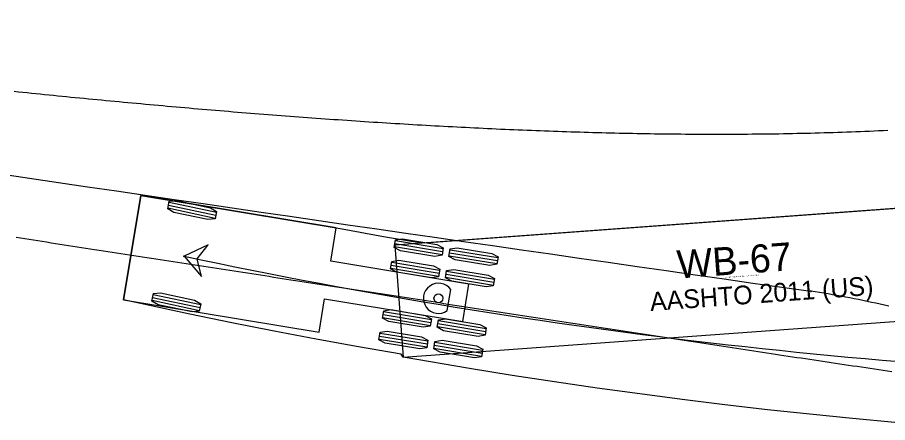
# Model space of a CAD drawing. Extents: x 2175591 to 2194071, y 76570 to 86955.
# Drawn here: x 2192756.8 to 2192822.6, y 86760 to 86790.7 of the extents above; entities that cross this region are included whole.
import ezdxf

# ---------------------------------------------------------------- set-up
doc = ezdxf.new("R2010")
doc.units = 0
doc.layers.add('-NOPLT', color=7, linetype='Continuous')
doc.layers.add('C-UTIL-STRM-TEXT', color=7, linetype='Continuous')

msp = doc.modelspace()

# ---------------------------------------------------------------- linework, layer by layer
at = {"layer": '-NOPLT'}
for points in [[(2192756.506, 86785.068), (2192756.837, 86785.034), (2192757.168, 86785), (2192757.499, 86784.966), (2192757.83, 86784.933), (2192758.161, 86784.899), (2192758.492, 86784.866), (2192758.824, 86784.833), (2192759.155, 86784.799), (2192759.486, 86784.766), (2192759.817, 86784.733), (2192760.149, 86784.701), (2192760.48, 86784.668), (2192760.811, 86784.635), (2192761.142, 86784.603), (2192761.474, 86784.571), (2192761.805, 86784.538), (2192762.137, 86784.506), (2192762.468, 86784.474), (2192762.799, 86784.443), (2192763.131, 86784.411), (2192763.462, 86784.379), (2192763.794, 86784.348), (2192764.125, 86784.317), (2192764.457, 86784.286), (2192764.788, 86784.255), (2192765.119, 86784.224), (2192765.451, 86784.193), (2192765.782, 86784.162), (2192766.114, 86784.132), (2192766.445, 86784.102), (2192766.777, 86784.071), (2192767.109, 86784.041), (2192767.44, 86784.011), (2192767.772, 86783.982), (2192768.103, 86783.952), (2192768.435, 86783.923), (2192768.766, 86783.893), (2192769.098, 86783.864), (2192769.43, 86783.835), (2192769.761, 86783.806), (2192770.093, 86783.778), (2192770.424, 86783.749), (2192770.756, 86783.721), (2192771.088, 86783.692), (2192771.419, 86783.664), (2192771.751, 86783.636), (2192772.083, 86783.609), (2192772.415, 86783.581), (2192772.746, 86783.553), (2192773.078, 86783.526), (2192773.41, 86783.499), (2192773.742, 86783.472), (2192774.073, 86783.445), (2192774.405, 86783.419), (2192774.737, 86783.392), (2192775.069, 86783.366), (2192775.4, 86783.34), (2192775.732, 86783.314), (2192776.064, 86783.288), (2192776.396, 86783.262), (2192776.728, 86783.237), (2192777.06, 86783.211), (2192777.392, 86783.186), (2192777.724, 86783.161), (2192778.055, 86783.137), (2192778.387, 86783.112), (2192778.719, 86783.088), (2192779.051, 86783.063), (2192779.383, 86783.039), (2192779.715, 86783.016), (2192780.047, 86782.992), (2192780.379, 86782.968), (2192780.711, 86782.945), (2192781.043, 86782.922), (2192781.375, 86782.899), (2192781.707, 86782.876), (2192782.039, 86782.854), (2192782.371, 86782.832), (2192782.703, 86782.81), (2192783.035, 86782.788), (2192783.368, 86782.766), (2192783.7, 86782.744), (2192784.032, 86782.723), (2192784.364, 86782.702), (2192784.696, 86782.681), (2192785.028, 86782.66), (2192785.36, 86782.64), (2192785.692, 86782.62), (2192786.025, 86782.6), (2192786.357, 86782.58), (2192786.689, 86782.56), (2192787.021, 86782.541), (2192787.353, 86782.521), (2192787.686, 86782.502), (2192788.018, 86782.484), (2192788.35, 86782.465), (2192788.682, 86782.447), (2192789.014, 86782.429), (2192789.347, 86782.411), (2192789.679, 86782.393), (2192790.011, 86782.376), (2192790.343, 86782.359), (2192790.676, 86782.342), (2192791.008, 86782.325), (2192791.34, 86782.309), (2192791.673, 86782.293), (2192792.005, 86782.277), (2192792.337, 86782.261), (2192792.67, 86782.245), (2192793.002, 86782.23), (2192793.334, 86782.215), (2192793.667, 86782.2), (2192793.999, 86782.186), (2192794.331, 86782.172), (2192794.664, 86782.158), (2192794.996, 86782.144), (2192795.329, 86782.131), (2192795.661, 86782.117), (2192795.993, 86782.104), (2192796.326, 86782.092), (2192796.658, 86782.079), (2192796.991, 86782.067), (2192797.323, 86782.055), (2192797.655, 86782.044), (2192797.988, 86782.032), (2192798.32, 86782.021), (2192798.653, 86782.011), (2192798.985, 86782), (2192799.318, 86781.99), (2192799.65, 86781.98), (2192799.983, 86781.97), (2192800.315, 86781.961), (2192800.648, 86781.952), (2192800.98, 86781.943), (2192801.313, 86781.935), (2192801.645, 86781.927), (2192801.978, 86781.919), (2192802.311, 86781.911), (2192802.643, 86781.904), (2192802.976, 86781.897), (2192803.309, 86781.891), (2192803.642, 86781.884), (2192803.975, 86781.878), (2192804.308, 86781.873), (2192804.641, 86781.867), (2192804.974, 86781.862), (2192805.307, 86781.857), (2192805.641, 86781.853), (2192805.974, 86781.849), (2192806.308, 86781.845), (2192806.642, 86781.842), (2192806.976, 86781.839), (2192807.31, 86781.836), (2192807.645, 86781.834), (2192807.979, 86781.832), (2192808.314, 86781.83), (2192808.649, 86781.829), (2192808.985, 86781.828), (2192809.32, 86781.827), (2192809.656, 86781.827), (2192809.992, 86781.827), (2192810.328, 86781.827), (2192810.665, 86781.828), (2192811.002, 86781.829), (2192811.339, 86781.831), (2192811.677, 86781.833), (2192812.014, 86781.835), (2192812.353, 86781.838), (2192812.691, 86781.841), (2192813.03, 86781.845), (2192813.369, 86781.849), (2192813.709, 86781.853), (2192814.048, 86781.858), (2192814.388, 86781.863), (2192814.729, 86781.869), (2192815.07, 86781.875), (2192815.411, 86781.882), (2192815.752, 86781.889), (2192816.094, 86781.896), (2192816.435, 86781.904), (2192816.778, 86781.912), (2192817.12, 86781.921), (2192817.463, 86781.93), (2192817.806, 86781.94), (2192818.149, 86781.95), (2192818.492, 86781.96), (2192818.836, 86781.971), (2192819.179, 86781.983), (2192819.523, 86781.995), (2192819.867, 86782.007), (2192820.211, 86782.021), (2192820.556, 86782.034), (2192820.9, 86782.048), (2192821.244, 86782.063), (2192821.589, 86782.078), (2192821.933, 86782.093), (2192822.277, 86782.109), (2192822.622, 86782.126)], [(2192793.995, 86768.245), (2192793.664, 86768.296), (2192793.333, 86768.347), (2192793.003, 86768.398), (2192792.672, 86768.449), (2192792.341, 86768.5), (2192792.01, 86768.551), (2192791.679, 86768.602), (2192791.348, 86768.653), (2192791.018, 86768.704), (2192790.687, 86768.755), (2192790.356, 86768.806), (2192790.025, 86768.857), (2192789.695, 86768.908), (2192789.364, 86768.959), (2192789.033, 86769.01), (2192788.703, 86769.061), (2192788.372, 86769.112), (2192788.041, 86769.163), (2192787.711, 86769.215), (2192787.38, 86769.266), (2192787.049, 86769.317), (2192786.719, 86769.368), (2192786.388, 86769.419), (2192786.057, 86769.47), (2192785.727, 86769.521), (2192785.396, 86769.572), (2192785.066, 86769.623), (2192784.735, 86769.674), (2192784.405, 86769.725), (2192784.074, 86769.776), (2192783.744, 86769.827), (2192783.413, 86769.878), (2192783.083, 86769.929), (2192782.752, 86769.98), (2192782.422, 86770.031), (2192782.091, 86770.083), (2192781.761, 86770.134), (2192781.43, 86770.185), (2192781.1, 86770.236), (2192780.769, 86770.287), (2192780.439, 86770.338), (2192780.109, 86770.389), (2192779.778, 86770.44), (2192779.448, 86770.491), (2192779.117, 86770.542), (2192778.787, 86770.593), (2192778.457, 86770.644), (2192778.126, 86770.695), (2192777.796, 86770.746), (2192777.466, 86770.797), (2192777.135, 86770.848), (2192776.805, 86770.899), (2192776.475, 86770.95), (2192776.144, 86771.001), (2192775.814, 86771.052), (2192775.484, 86771.103), (2192775.154, 86771.154), (2192774.823, 86771.205), (2192774.493, 86771.256), (2192774.163, 86771.307), (2192773.832, 86771.358), (2192773.502, 86771.409), (2192773.172, 86771.46), (2192772.842, 86771.511), (2192772.511, 86771.562), (2192772.181, 86771.613), (2192771.851, 86771.664), (2192771.521, 86771.715), (2192771.19, 86771.766), (2192770.86, 86771.817), (2192770.53, 86771.867), (2192770.2, 86771.918), (2192769.87, 86771.969), (2192769.539, 86772.02), (2192769.209, 86772.071), (2192768.879, 86772.122), (2192768.549, 86772.173), (2192768.219, 86772.224), (2192767.889, 86772.275), (2192767.558, 86772.326), (2192767.228, 86772.377), (2192766.898, 86772.428), (2192766.568, 86772.478), (2192766.238, 86772.529), (2192765.908, 86772.58), (2192765.578, 86772.631), (2192765.248, 86772.682), (2192764.917, 86772.733), (2192764.587, 86772.784), (2192764.257, 86772.835), (2192763.927, 86772.885), (2192763.597, 86772.936), (2192763.267, 86772.987), (2192762.937, 86773.038), (2192762.607, 86773.089), (2192762.277, 86773.14), (2192761.947, 86773.19), (2192761.617, 86773.241), (2192761.286, 86773.292), (2192760.956, 86773.343), (2192760.626, 86773.394), (2192760.296, 86773.445), (2192759.966, 86773.495), (2192759.636, 86773.546), (2192759.306, 86773.597), (2192758.976, 86773.648), (2192758.646, 86773.698), (2192758.316, 86773.749), (2192757.986, 86773.8), (2192757.656, 86773.851), (2192757.327, 86773.902), (2192756.997, 86773.952), (2192756.667, 86774.003)], [(2192822.694, 86768.81), (2192822.37, 86768.887), (2192822.045, 86768.962), (2192821.72, 86769.037), (2192821.395, 86769.109), (2192821.069, 86769.18), (2192820.743, 86769.25), (2192820.417, 86769.317), (2192820.09, 86769.384), (2192819.763, 86769.448), (2192819.436, 86769.511), (2192819.108, 86769.572), (2192818.78, 86769.631), (2192818.452, 86769.688), (2192818.123, 86769.744), (2192817.794, 86769.797), (2192817.465, 86769.849), (2192817.135, 86769.898), (2192816.805, 86769.946)], [(2192822.925, 86763.864), (2192822.597, 86763.912), (2192822.27, 86763.96), (2192821.943, 86764.008), (2192821.616, 86764.056), (2192821.289, 86764.104), (2192820.962, 86764.152), (2192820.636, 86764.2), (2192820.31, 86764.248), (2192819.984, 86764.296), (2192819.658, 86764.344), (2192819.332, 86764.393), (2192819.006, 86764.441), (2192818.68, 86764.489), (2192818.354, 86764.538), (2192818.029, 86764.586), (2192817.703, 86764.635), (2192817.377, 86764.683), (2192817.052, 86764.732), (2192816.726, 86764.78), (2192816.4, 86764.829), (2192816.074, 86764.878), (2192815.749, 86764.926), (2192815.423, 86764.975), (2192815.097, 86765.024), (2192814.771, 86765.073), (2192814.444, 86765.122), (2192814.118, 86765.171), (2192813.792, 86765.22), (2192813.465, 86765.269), (2192813.138, 86765.319), (2192812.812, 86765.368), (2192812.485, 86765.417), (2192812.157, 86765.467), (2192811.83, 86765.516), (2192811.503, 86765.566), (2192811.175, 86765.615), (2192810.847, 86765.665), (2192810.519, 86765.714), (2192810.191, 86765.764), (2192809.862, 86765.814), (2192809.534, 86765.864), (2192809.205, 86765.914), (2192808.876, 86765.964), (2192808.547, 86766.014), (2192808.218, 86766.064), (2192807.889, 86766.114), (2192807.559, 86766.164), (2192807.229, 86766.214), (2192806.9, 86766.265), (2192806.57, 86766.315), (2192806.24, 86766.365), (2192805.909, 86766.416), (2192805.579, 86766.466), (2192805.249, 86766.516), (2192804.918, 86766.567), (2192804.588, 86766.617), (2192804.257, 86766.668), (2192803.926, 86766.719), (2192803.595, 86766.769), (2192803.265, 86766.82), (2192802.934, 86766.871), (2192802.603, 86766.921), (2192802.272, 86766.972), (2192801.941, 86767.023), (2192801.61, 86767.074), (2192801.278, 86767.124), (2192800.947, 86767.175), (2192800.616, 86767.226), (2192800.285, 86767.277), (2192799.954, 86767.328), (2192799.623, 86767.379), (2192799.292, 86767.429), (2192798.961, 86767.48), (2192798.629, 86767.531), (2192798.298, 86767.582), (2192797.967, 86767.633), (2192797.636, 86767.684), (2192797.305, 86767.735), (2192796.974, 86767.786), (2192796.643, 86767.837), (2192796.312, 86767.888), (2192795.981, 86767.939), (2192795.65, 86767.99), (2192795.319, 86768.041), (2192794.988, 86768.092), (2192794.657, 86768.143), (2192794.326, 86768.194), (2192793.995, 86768.245)]]:
    msp.add_lwpolyline(points, dxfattribs=at)
msp.add_circle((2192816.805, 86769.946), 0.0417, dxfattribs=at)
msp.add_circle((2192816.805, 86769.946), 0.0417, dxfattribs=at)
msp.add_arc((2194674.65, 99822.88), 13184.487, 261.2840472, 261.8994114, dxfattribs=at)
at = {"layer": 'C-UTIL-STRM-TEXT'}
for p, q in [((2192766.095, 86777.196), (2192764.789, 86769.303)), ((2192780.894, 86774.748), (2192766.095, 86777.196)), ((2192838.185, 86777.295), (2192785.325, 86773.435)), ((2192768.242, 86776.693), (2192771.828, 86775.929)), ((2192768.146, 86776.245), (2192771.732, 86775.481)), ((2192768.194, 86776.469), (2192771.78, 86775.705)), ((2192780.475, 86772.216), (2192780.894, 86774.748)), ((2192785.287, 86773.325), (2192788.904, 86772.726)), ((2192785.324, 86773.551), (2192788.942, 86772.952)), ((2192785.325, 86773.435), (2192785.945, 86764.957)), ((2192785.362, 86773.777), (2192788.979, 86773.179)), ((2192789.431, 86772.639), (2192793.048, 86772.041)), ((2192789.468, 86772.865), (2192793.086, 86772.267)), ((2192789.505, 86773.091), (2192793.123, 86772.493)), ((2192790.933, 86770.486), (2192780.475, 86772.216)), ((2192785.055, 86771.923), (2192788.673, 86771.325)), ((2192785.092, 86772.149), (2192788.71, 86771.551)), ((2192785.018, 86771.697), (2192788.635, 86771.098)), ((2192789.199, 86771.238), (2192792.816, 86770.639)), ((2192789.236, 86771.464), (2192792.854, 86770.865)), ((2192789.161, 86771.011), (2192792.779, 86770.413)), ((2192789.292, 86768.486), (2192789.556, 86770.08)), ((2192790.465, 86767.658), (2192790.933, 86770.486)), ((2192764.789, 86769.303), (2192779.588, 86766.855)), ((2192764.789, 86769.303), (2192764.789, 86769.303)), ((2192766.949, 86769.263), (2192770.536, 86768.502)), ((2192766.997, 86769.487), (2192770.583, 86768.726)), ((2192767.044, 86769.712), (2192770.631, 86768.95)), ((2192779.588, 86766.855), (2192780.007, 86769.388)), ((2192780.007, 86769.388), (2192790.465, 86767.658)), ((2192785.945, 86764.957), (2192838.804, 86768.818)), ((2192784.4, 86767.964), (2192788.018, 86767.366)), ((2192784.438, 86768.19), (2192788.055, 86767.592)), ((2192784.475, 86768.416), (2192788.093, 86767.818)), ((2192788.544, 86767.279), (2192792.161, 86766.68)), ((2192788.581, 86767.505), (2192792.199, 86766.907)), ((2192788.619, 86767.731), (2192792.236, 86767.133)), ((2192784.206, 86766.789), (2192787.823, 86766.19)), ((2192784.131, 86766.336), (2192787.749, 86765.738)), ((2192784.168, 86766.562), (2192787.786, 86765.964)), ((2192788.35, 86766.103), (2192791.967, 86765.505)), ((2192788.275, 86765.651), (2192791.892, 86765.053)), ((2192788.312, 86765.877), (2192791.93, 86765.279)), ((2192785.945, 86764.957), (2192785.945, 86764.957))]:
    msp.add_line(p, q, dxfattribs=at)
msp.add_lwpolyline([(2192823.171, 86760.02), (2192819.955, 86760.32), (2192816.737, 86760.644), (2192813.516, 86760.992), (2192810.295, 86761.365), (2192807.074, 86761.762), (2192803.853, 86762.182), (2192800.633, 86762.627), (2192797.415, 86763.095), (2192794.199, 86763.586), (2192790.985, 86764.101), (2192785.945, 86764.957), (2192785.791, 86765.183), (2192782.584, 86765.743), (2192779.381, 86766.327), (2192776.184, 86766.935), (2192772.995, 86767.566), (2192769.818, 86768.219), (2192764.789, 86769.303), (2192766.095, 86777.196), (2192781.335, 86774.666), (2192784.454, 86774.1), (2192787.185, 86773.625), (2192787.58, 86773.6), (2192836.449, 86777.187)], dxfattribs=at)
for points in [[(2192768.134, 86776.189), (2192768.254, 86776.749), (2192768.791, 86776.81), (2192771.374, 86776.261), (2192771.84, 86775.985), (2192771.721, 86775.426), (2192771.183, 86775.364), (2192768.601, 86775.914)], [(2192785.278, 86773.269), (2192785.371, 86773.833), (2192785.906, 86773.919), (2192788.51, 86773.488), (2192788.989, 86773.235), (2192788.895, 86772.67), (2192788.361, 86772.584), (2192785.756, 86773.015)], [(2192769.388, 86772.597), (2192770.687, 86771.076), (2192770.367, 86772.389), (2192771.194, 86773.458)], [(2192789.421, 86772.583), (2192789.515, 86773.148), (2192790.049, 86773.234), (2192792.654, 86772.803), (2192793.132, 86772.549), (2192793.039, 86771.985), (2192792.504, 86771.899), (2192789.9, 86772.329)], [(2192785.008, 86771.641), (2192785.102, 86772.205), (2192785.636, 86772.291), (2192788.241, 86771.86), (2192788.719, 86771.607), (2192788.626, 86771.042), (2192788.091, 86770.956), (2192785.487, 86771.387)], [(2192789.152, 86770.955), (2192789.245, 86771.52), (2192789.78, 86771.606), (2192792.385, 86771.175), (2192792.863, 86770.921), (2192792.77, 86770.357), (2192792.235, 86770.271), (2192789.63, 86770.702)], [(2192766.937, 86769.208), (2192767.056, 86769.767), (2192767.594, 86769.829), (2192770.176, 86769.281), (2192770.643, 86769.006), (2192770.524, 86768.446), (2192769.986, 86768.384), (2192767.404, 86768.932)], [(2192784.391, 86767.908), (2192784.484, 86768.472), (2192785.019, 86768.559), (2192787.624, 86768.128), (2192788.102, 86767.874), (2192788.009, 86767.31), (2192787.474, 86767.224), (2192784.869, 86767.654)], [(2192788.535, 86767.223), (2192788.628, 86767.787), (2192789.163, 86767.873), (2192791.767, 86767.442), (2192792.246, 86767.189), (2192792.152, 86766.624), (2192791.618, 86766.538), (2192789.013, 86766.969)], [(2192784.122, 86766.28), (2192784.215, 86766.845), (2192784.75, 86766.931), (2192787.354, 86766.5), (2192787.833, 86766.246), (2192787.739, 86765.682), (2192787.205, 86765.596), (2192784.6, 86766.026)], [(2192788.265, 86765.595), (2192788.359, 86766.159), (2192788.893, 86766.245), (2192791.498, 86765.815), (2192791.976, 86765.561), (2192791.883, 86764.996), (2192791.348, 86764.91), (2192788.744, 86765.341)]]:
    msp.add_lwpolyline(points, close=True, dxfattribs=at)
for centre, radius in [((2192769.388, 86772.597), 0.0417), ((2192788.627, 86769.415), 0.34)]:
    msp.add_circle(centre, radius, dxfattribs=at)
for centre, radius, start, end in [((2192859.136, 87194.645), 431.485, 257.995, 269.07123), ((2192788.627, 86769.415), 1.143, 35.60786, 305.60786)]:
    msp.add_arc(centre, radius, start, end, dxfattribs=at)

# ---------------------------------------------------------------- texts
for s, height, p in [('WB-67', 2.125, (2192806.754, 86770.909)), ('(c) 2019 Transoft Solutions, Inc. All rights reserved.', 0.085, (2192810.34, 86770.958)), ('AASHTO 2011 (US)', 1.41667, (2192804.676, 86768.449))]:
    msp.add_text(s, height=height, rotation=4.17716, dxfattribs=at).set_placement(p)

doc.saveas('drawing.dxf')
